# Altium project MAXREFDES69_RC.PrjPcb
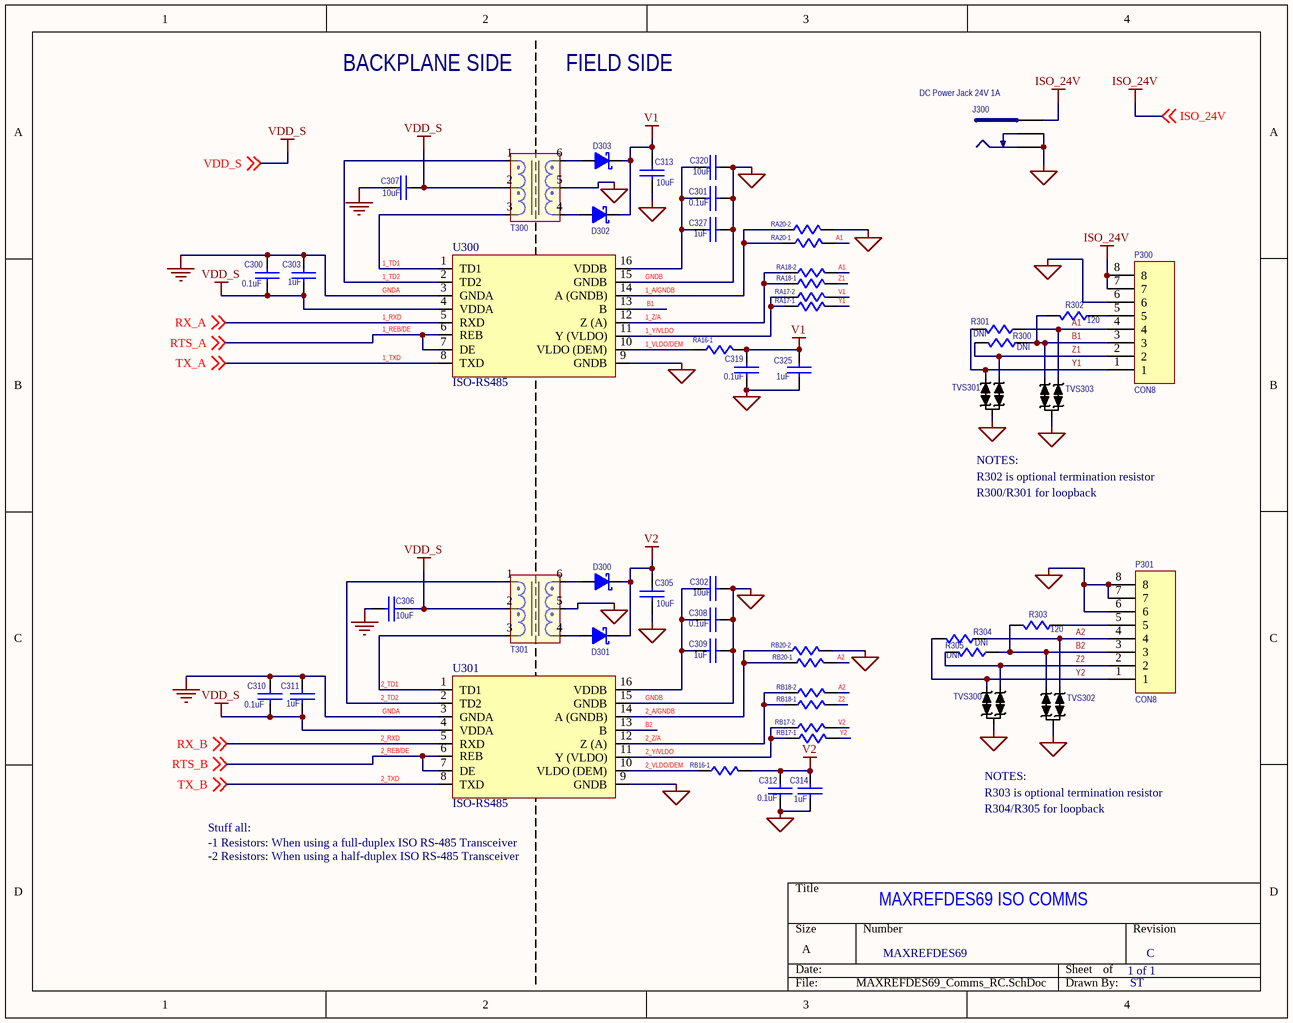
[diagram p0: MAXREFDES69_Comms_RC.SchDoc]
4 sheets, 104 parts. Net scope: global (net labels, ports and power ports of the same name join across sheets).
Board file: MAXREFDES69_PCB_RC.PcbDoc
Sheets:
  MAXREFDES69_Comms_RC.SchDoc
  MAXREFDES69_Power_RC.SchDoc
  MAXREFDES69_Processor_RC.SchDoc
  MAXREFDES69_USB_RC.SchDoc

## Sheet MAXREFDES69_Comms_RC.SchDoc
size A

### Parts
C300  value 0.1uF  [0402]  (hidden comment: CAP)
C301  value 0.1uF  [0402]  (hidden comment: CAP)
C302  value 10uF  [0402]  (hidden comment: CAP)
C303  value 1uF  [0402]  (hidden comment: CAP)
C305  value 10uF  [0402]  (hidden comment: CAP)
C306  value 10uF  [0402]  (hidden comment: CAP)
C307  value 10uF  [0402]  (hidden comment: CAP)
C308  value 0.1uF  [0402]  (hidden comment: CAP)
C309  value 1uF  [0402]  (hidden comment: CAP)
C310  value 0.1uF  [0402]  (hidden comment: CAP)
C311  value 1uF  [0402]  (hidden comment: CAP)
C312  value 0.1uF  [0402]  (hidden comment: CAP)
C313  value 10uF  [0402]  (hidden comment: CAP)
C314  value 1uF  [0402]  (hidden comment: CAP)
C319  value 0.1uF  [0402]  (hidden comment: CAP)
C320  value 10uF  [0402]  (hidden comment: CAP)
C325  value 1uF  [0402]  (hidden comment: CAP)
C327  value 1uF  [0402]  (hidden comment: CAP)
D300  DIODE_SCHOTTKY  [SOD123]  (value not drawn)
D301  DIODE_SCHOTTKY  [SOD123]  (value not drawn)
D302  DIODE_SCHOTTKY  [SOD123]  (value not drawn)
D303  DIODE_SCHOTTKY  [SOD123]  (value not drawn)
J300  DC Power Jack 24V 1A  [JACK\CUI\PJ-202AH]
P300  CON8  [TB\8POS\PHOENIXCONTACT\1771088]
P301  CON8  [TB\8POS\PHOENIXCONTACT\1771088]
R300  value DNI  [R0402]  (hidden comment: RES1)
R301  value DNI  [R0402]  (hidden comment: RES1)
R302  value 120  [R0402]  (hidden comment: RES1)
R303  value 120  [R0402]  (hidden comment: RES1)
R304  value DNI  [R0402]  (hidden comment: RES1)
R305  value DNI  [R0402]  (hidden comment: RES1)
RA16-1  RES1  [R0402]  (value not drawn)
RA17-1  RES1  [R0402]  (value not drawn)
RA17-2  RES1  [R0402]  (value not drawn)
RA18-1  RES1  [R0402]  (value not drawn)
RA18-2  RES1  [R0402]  (value not drawn)
RA20-1  RES1  [R0402]  (value not drawn)
RA20-2  RES1  [R0402]  (value not drawn)
RB16-1  RES1  [R0402]  (value not drawn)
RB17-1  RES1  [R0402]  (value not drawn)
RB17-2  RES1  [R0402]  (value not drawn)
RB18-1  RES1  [R0402]  (value not drawn)
RB18-2  RES1  [R0402]  (value not drawn)
RB20-1  RES1  [R0402]  (value not drawn)
RB20-2  RES1  [R0402]  (value not drawn)
T300  Transformer  [XFMR (WURTH 750315225)]  (value not drawn)
T301  Transformer  [XFMR (WURTH 750315225)]  (value not drawn)
TVS300  TVS SM712  [SM712 TVS]  (value not drawn)
TVS301  TVS SM712  [SM712 TVS]  (value not drawn)
TVS302  TVS SM712  [SM712 TVS]  (value not drawn)
TVS303  TVS SM712  [SM712 TVS]  (value not drawn)
U300  ISO-RS485  [SOIC 16W(W16M-9/10)]
U301  ISO-RS485  [SOIC 16W(W16M-9/10)]

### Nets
GND_S: C300.1 C303.1 C306.2 C307.2 C310.1 C311.1 U300.3(GNDA) U301.3(GNDA)  [also labelled GNDA]
GNDB: C301.1 C302.1 C305.2 C308.1 C309.1 C312.1 C313.2 C314.1 C319.1 C320.1 C325.1 C327.1 J300.2(RETN) J300.3(SENSE) P300.6 P301.6 P301.7 P301.8 RA20-2.2 RB20-2.2 T300.5 T301.5 TVS300.3(K) TVS301.3(K) TVS302.3(K) TVS303.3(K) U300.9(GNDB) U300.15(GNDB) U301.9(GNDB) U301.15(GNDB)  [also labelled ISO_GND]
ISO_24V: J300.1(CTR) P300.7 P300.8 ; off-sheet ISO_24V
V1: C313.1 C319.2 C325.2 D302.2(K) D303.2(K) RA16-1.2 RA17-2.2
V2: C305.1 C312.2 C314.2 D300.2(K) D301.2(K) RB16-1.2 RB17-2.2
VDD_S: C300.2 C303.2 C306.1 C307.1 C310.2 C311.2 T300.2 T301.2 U300.4(VDDA) U301.4(VDDA) ; off-sheet VDD_S
1_A/GNDB: RA20-1.1 RA20-2.1 U300.14(A_(GNDB))
1_REB/DE: U300.6(REB) U300.7(DE) ; off-sheet RTS_A  [also labelled RTS_A]
1_RXD: U300.5(RXD) ; off-sheet RX_A  [also labelled RX_A]
1_TD1: T300.3 U300.1(TD1)
1_TD2: T300.1 U300.2(TD2)
1_TXD: U300.8(TXD) ; off-sheet TX_A  [also labelled TX_A]
1_VLDO/DEM: RA16-1.1 U300.10(VLDO_(DEM))
1_Y/VLDO: RA17-1.1 RA17-2.1 U300.11(Y_(VLDO))
1_Z/A: RA18-1.1 RA18-2.1 U300.12(Z_(A))
2_A/GNDB: RB20-1.1 RB20-2.1 U301.14(A_(GNDB))
2_REB/DE: U301.6(REB) U301.7(DE) ; off-sheet RTS_B  [also labelled RTS_B]
2_RXD: U301.5(RXD) ; off-sheet RX_B  [also labelled RX_B]
2_TD1: T301.3 U301.1(TD1)
2_TD2: T301.1 U301.2(TD2)
2_TXD: U301.8(TXD) ; off-sheet TX_B  [also labelled TX_B]
2_VLDO/DEM: RB16-1.1 U301.10(VLDO_(DEM))
2_Y/VLDO: RB17-1.1 RB17-2.1 U301.11(Y_(VLDO))
2_Z/A: RB18-1.1 RB18-2.1 U301.12(Z_(A))
A1: P300.4 R301.1 RA18-2.2 RA20-1.2 TVS303.2(K)
A2: P301.4 R304.1 RB18-2.2 RB20-1.2 TVS302.2(K)
B1: P300.3 R300.1 R302.2 TVS303.1(K) U300.13(B)
B2: P301.3 R303.2 R305.1 TVS302.1(K) U301.13(B)
Y1: P300.1 R301.2 RA17-1.2 TVS301.1(K)
Y2: P301.1 R304.2 RB17-1.2 TVS300.1(K)
Z1: P300.2 R300.2 RA18-1.2 TVS301.2(K)
Z2: P301.2 R305.2 RB18-1.2 TVS300.2(K)
NetC301_2: C301.2 C320.2 C327.2 U300.16(VDDB)
NetC302_2: C302.2 C308.2 C309.2 U301.16(VDDB)
NetD300_1: D300.1(A) T301.6
NetD301_1: D301.1(A) T301.4
NetD302_1: D302.1(A) T300.4
NetD303_1: D303.1(A) T300.6
NetP300_5: P300.5 R302.1
NetP301_5: P301.5 R303.1

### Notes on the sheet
- BACKPLANE SIDE
- FIELD SIDE
- NOTES:
- R302 is optional termination resistor
- R300/R301 for loopback
- Stuff all:
- R303 is optional termination resistor
- R304/R305 for loopback
- (near U301) -1 Resistors: When using a full-duplex ISO RS-485 Transceiver
- -2 Resistors: When using a half-duplex ISO RS-485 Transceiver
- MAXREFDES69 ISO COMMS
- MAXREFDES69
- 1 of 1
- C
- ST

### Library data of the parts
C300-C303 C305-C314 C319 C320 C325 C327 = CAP: Capacitor
D300-D303 = DIODE_SCHOTTKY: Schottky Diode
J300 = DC Power Jack 24V 1A: DC Power Jack 24V 5A - CUI PJ-202AH
P300 P301 = CON8: Header, 8-pin
T300 T301 = Transformer (RU77)
U300 U301 = ISO_RS485_Combo_1: NOTE: Pin numbers with no notation are RU77/84/85 with TD; NOTE: Pin numbers in () are RU86 (Full duplex)

## Sheet MAXREFDES69_Power_RC.SchDoc
size B
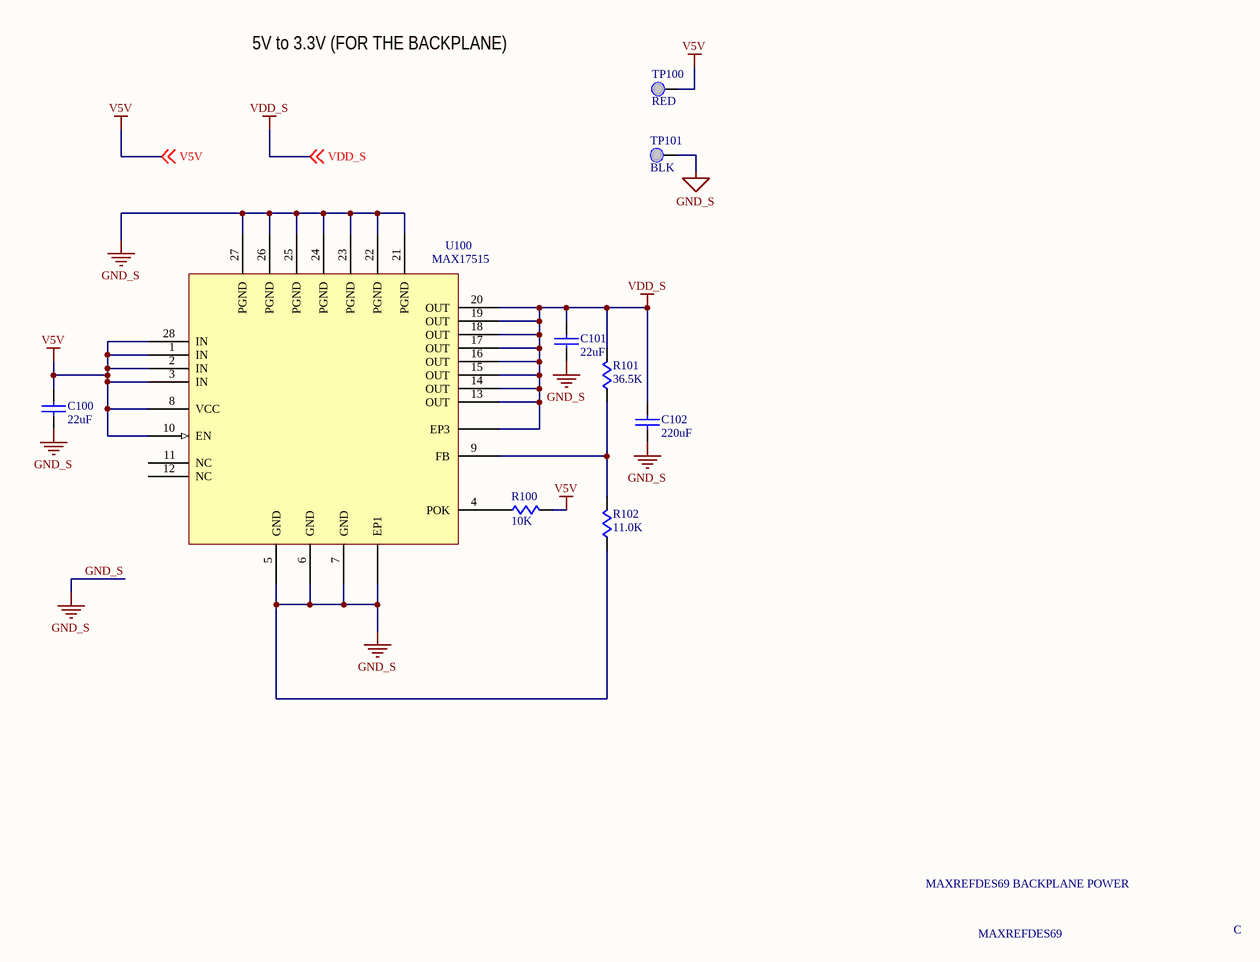
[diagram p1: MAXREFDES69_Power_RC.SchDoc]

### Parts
C100  value 22uF  [1206]  (hidden comment: CAP)
C101  value 22uF  [1206]  (hidden comment: CAP)
C102  value 220uF  [CAP\PANA\TPE\D2E]  (hidden comment: CAP)
R100  value 10K  [R0402]  (hidden comment: RES1)
R101  value 36.5K  [R0402]  (hidden comment: RES1)
R102  value 11.0K  [R0402]  (hidden comment: RES1)
TP100  RED  [TestPoint]
TP101  BLK  [TestPoint]
U100  MAX17515  [SIP28\LGA\6.5X10MM\28L\3EP\L286510+1]

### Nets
EP2: U100.30(EP2) U100.35(EP2) U100.36(EP2) U100.37(EP2)
GND_S: C100.2 C101.2 C102.2 R102.1 TP101.1(PIN) U100.5(GND) U100.6(GND) U100.7(GND) U100.21(PGND) U100.22(PGND) U100.23(PGND) U100.24(PGND) U100.25(PGND) U100.26(PGND) U100.27(PGND) U100.31(EP1) U100.38(EP1) U100.39(EP1) U100.40(EP1) U100.41(EP1) U100.42(EP1)
V5V: C100.1 R100.2 TP100.1(PIN) U100.1(IN) U100.2(IN) U100.3(IN) U100.8(VCC) U100.10(EN) U100.28(IN) ; off-sheet V5V
VDD_S: C101.1 C102.1 R101.2 U100.13(OUT) U100.14(OUT) U100.15(OUT) U100.16(OUT) U100.17(OUT) U100.18(OUT) U100.19(OUT) U100.20(OUT) U100.29(EP3) U100.32(EP3) U100.33(EP3) U100.34(EP3) ; off-sheet VDD_S
NetR100_1: R100.1 U100.4(POK)
NetR101_1: R101.1 R102.2 U100.9(FB)

Not connected (* = marked no-connect by the designer): U100 11(NC) 12(NC)

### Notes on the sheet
- 5V to 3.3V (FOR THE BACKPLANE)
- MAXREFDES69 BACKPLANE POWER
- MAXREFDES69
- C

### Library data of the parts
C100-C102 = CAP: Capacitor
TP100 TP101 = TESTPOINT: Test Point Loop

## Sheet MAXREFDES69_Processor_RC.SchDoc
size B
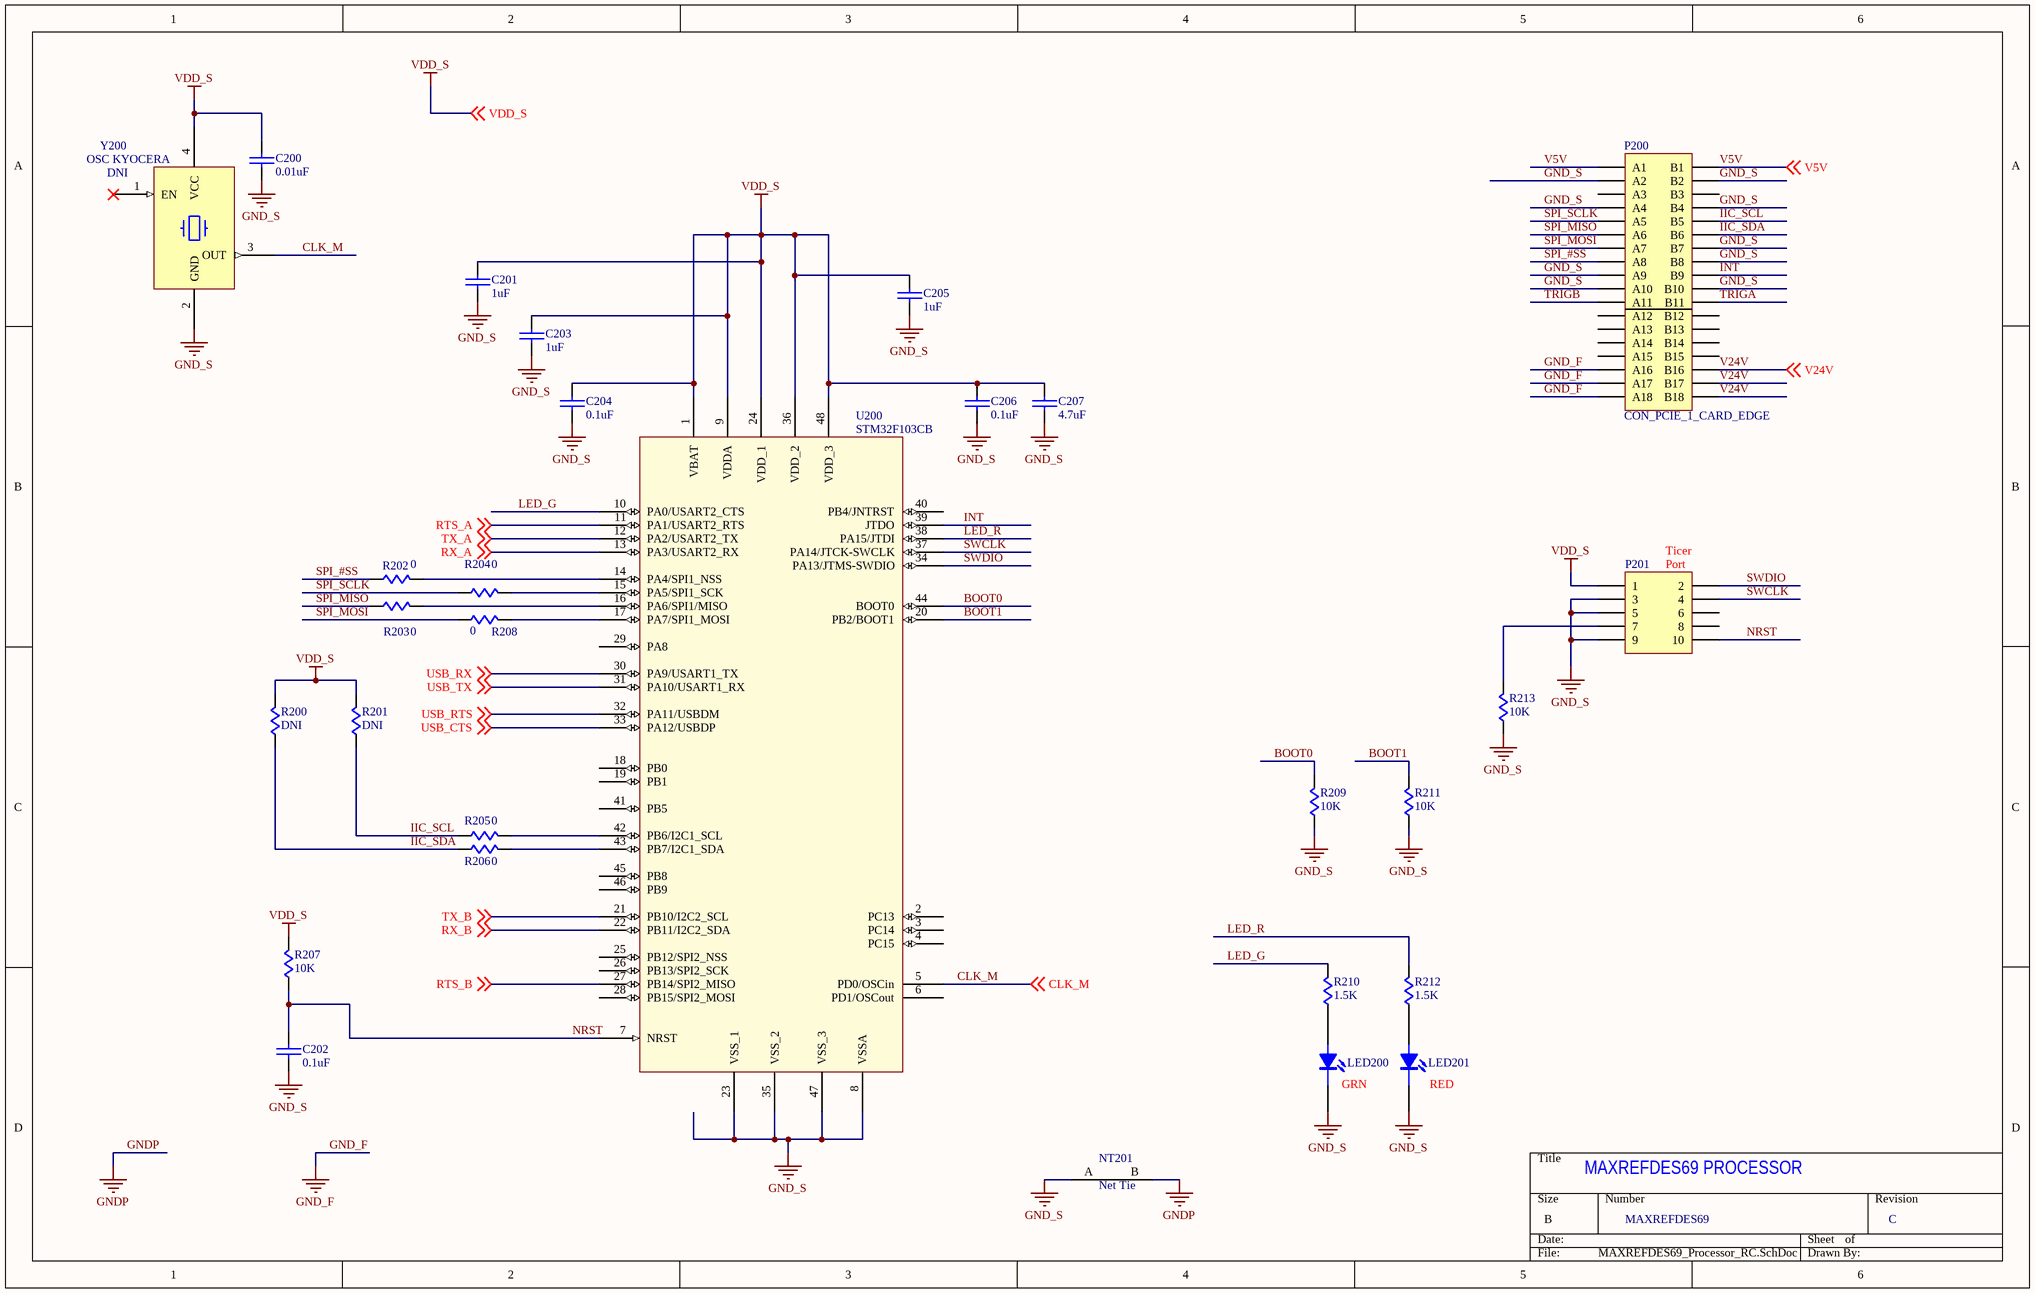
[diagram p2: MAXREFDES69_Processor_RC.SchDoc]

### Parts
C200  value 0.01uF  [0603]  (hidden comment: CAP)
C201  value 1uF  [0603]  (hidden comment: CAP)
C202  value 0.1uF  [0603]  (hidden comment: CAP)
C203  value 1uF  [0603]  (hidden comment: CAP)
C204  value 0.1uF  [0603]  (hidden comment: CAP)
C205  value 1uF  [0603]  (hidden comment: CAP)
C206  value 0.1uF  [0603]  (hidden comment: CAP)
C207  value 4.7uF  [0603]  (hidden comment: CAP)
LED200  LED  [LED\ROHM\SML-P1]  (value not drawn)
LED201  LED  [LED\ROHM\SML-P1]  (value not drawn)
NT201  Net Tie  [Net Tie Small 2]  (net tie, no BOM)
P200  CON_PCIE_1_CARD_EDGE  [CONN\PCI_EXP\36P\CARDEDGE\GLPMSS]
P201  HEADER 5X2  [CONN\SAMTEC\FTSH-105-01-L-DV-K]  (value not drawn)
R200  value DNI  [R0402]  (hidden comment: RES1)
R201  value DNI  [R0402]  (hidden comment: RES1)
R202  value 0  [R0402]  (hidden comment: RES1)
R203  value 0  [R0402]  (hidden comment: RES1)
R204  value 0  [R0402]  (hidden comment: RES1)
R205  value 0  [R0402]  (hidden comment: RES1)
R206  value 0  [R0402]  (hidden comment: RES1)
R207  value 10K  [R0402]  (hidden comment: RES1)
R208  value 0  [R0402]  (hidden comment: RES1)
R209  value 10K  [R0402]  (hidden comment: RES1)
R210  value 1.5K  [R0402]  (hidden comment: RES1)
R211  value 10K  [CC0402]  (hidden comment: CC0402)
R212  value 1.5K  [CC0402]  (hidden comment: RES1)
R213  value 10K  [R0402]  (hidden comment: RES1)
U200  STM32F103CB  [LQFP48 - ST Micro]
Y200  OSC KYOCERA  [XTAL\HOSONIC\2520]

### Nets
GND_F: P200.A16 P200.A17 P200.A18
GND_S: C200.2 C201.2 C202.2 C203.2 C204.2 C205.2 C206.2 C207.2 LED200.2(K) LED201.2(K) P200.A2 P200.A4 P200.A9 P200.A10 P200.B2 P200.B4 P200.B7 P200.B8 P200.B10 P201.3 P201.5 P201.9 R209.1 R211.1 R213.1 U200.8(VSSA) U200.23(VSS_1) U200.35(VSS_2) U200.47(VSS_3) Y200.2(GND)
V5V: P200.A1 P200.B1 ; off-sheet V5V
VDD_S: C200.1 C201.1 C203.1 C204.1 C205.1 C206.1 C207.1 P201.1 R200.2 R201.2 R207.2 U200.1(VBAT) U200.9(VDDA) U200.24(VDD_1) U200.36(VDD_2) U200.48(VDD_3) Y200.4(VCC) ; off-sheet VDD_S
BOOT0: R209.2 U200.44(BOOT0)
BOOT1: R211.2 U200.20(PB2/BOOT1)
CLK_M: U200.5(PD0/OSCin) Y200.3(OUT) ; off-sheet CLK_M
IIC_SCL: P200.B5 R201.1 R205.1
IIC_SDA: P200.B6 R200.1 R206.1
INT: P200.B9 U200.39(JTDO)
LED_G: R210.2 U200.10(PA0/USART2_CTS)
LED_R: R212.2 U200.38(PA15/JTDI)
NRST: C202.1 P201.10 R207.1 U200.7(NRST)
RTS_A: U200.11(PA1/USART2_RTS) ; off-sheet RTS_A  [project net 1_REB/DE]
RTS_B: U200.27(PB14/SPI2_MISO) ; off-sheet RTS_B  [project net 2_REB/DE]
RX_A: U200.13(PA3/USART2_RX) ; off-sheet RX_A  [project net 1_RXD]
RX_B: U200.22(PB11/I2C2_SDA) ; off-sheet RX_B  [project net 2_RXD]
SPI_#SS: P200.A8 R202.1
SPI_MISO: P200.A6 R203.1
SPI_MOSI: P200.A7 R208.1
SPI_SCLK: P200.A5 R204.1
SWCLK: P201.4 U200.37(PA14/JTCK-SWCLK)
SWDIO: P201.2 U200.34(PA13/JTMS-SWDIO)
TRIGA: P200.B11
TRIGB: P200.A11
TX_A: U200.12(PA2/USART2_TX) ; off-sheet TX_A  [project net 1_TXD]
TX_B: U200.21(PB10/I2C2_SCL) ; off-sheet TX_B  [project net 2_TXD]
USB_CTS: U200.33(PA12/USBDP) ; off-sheet USB_CTS
USB_RTS: U200.32(PA11/USBDM) ; off-sheet USB_RTS
USB_RX: U200.30(PA9/USART1_TX) ; off-sheet USB_RX
USB_TX: U200.31(PA10/USART1_RX) ; off-sheet USB_TX
V24V: P200.B16 P200.B17 P200.B18 ; off-sheet V24V
NetLED200_1: LED200.1(A) R210.1
NetLED201_1: LED201.1(A) R212.1
NetNT201_A: NT201.A NT201.B
NetP201_7: P201.7 R213.2
NetR202_2: R202.2 U200.14(PA4/SPI1_NSS)
NetR203_2: R203.2 U200.16(PA6/SPI1/MISO)
NetR204_2: R204.2 U200.15(PA5/SPI1_SCK)
NetR205_2: R205.2 U200.42(PB6/I2C1_SCL)
NetR206_2: R206.2 U200.43(PB7/I2C1_SDA)
NetR208_2: R208.2 U200.17(PA7/SPI1_MOSI)

Not connected (* = marked no-connect by the designer): P200 A3 A12 A13 A14 A15 B3 B12 B13 B14 B15; P201 6 8; U200 2(PC13) 3(PC14) 4(PC15) 6(PD1/OSCout) 18(PB0) 19(PB1) 25(PB12/SPI2_NSS) 26(PB13/SPI2_SCK) 28(PB15/SPI2_MOSI) 29(PA8) 40(PB4/JNTRST) 41(PB5) 45(PB8) 46(PB9); Y200 1(EN)*

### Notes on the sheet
- (near P201) Ticer
- (near P201) Port
- (near LED200) GRN
- (near LED201) RED
- MAXREFDES69 PROCESSOR
- MAXREFDES69
- C

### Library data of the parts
C200-C207 = CAP: Capacitor
P200 = CON_PCIE_1_STATIC: PCIE-1, FCI 10018783-10200TLF
R211 = RES1
U200 = STM32F103CB: STM32F103 Micorprocessor
Y200 = OSC_KYOCERA: Osc, Kyocera

## Sheet MAXREFDES69_USB_RC.SchDoc
size B
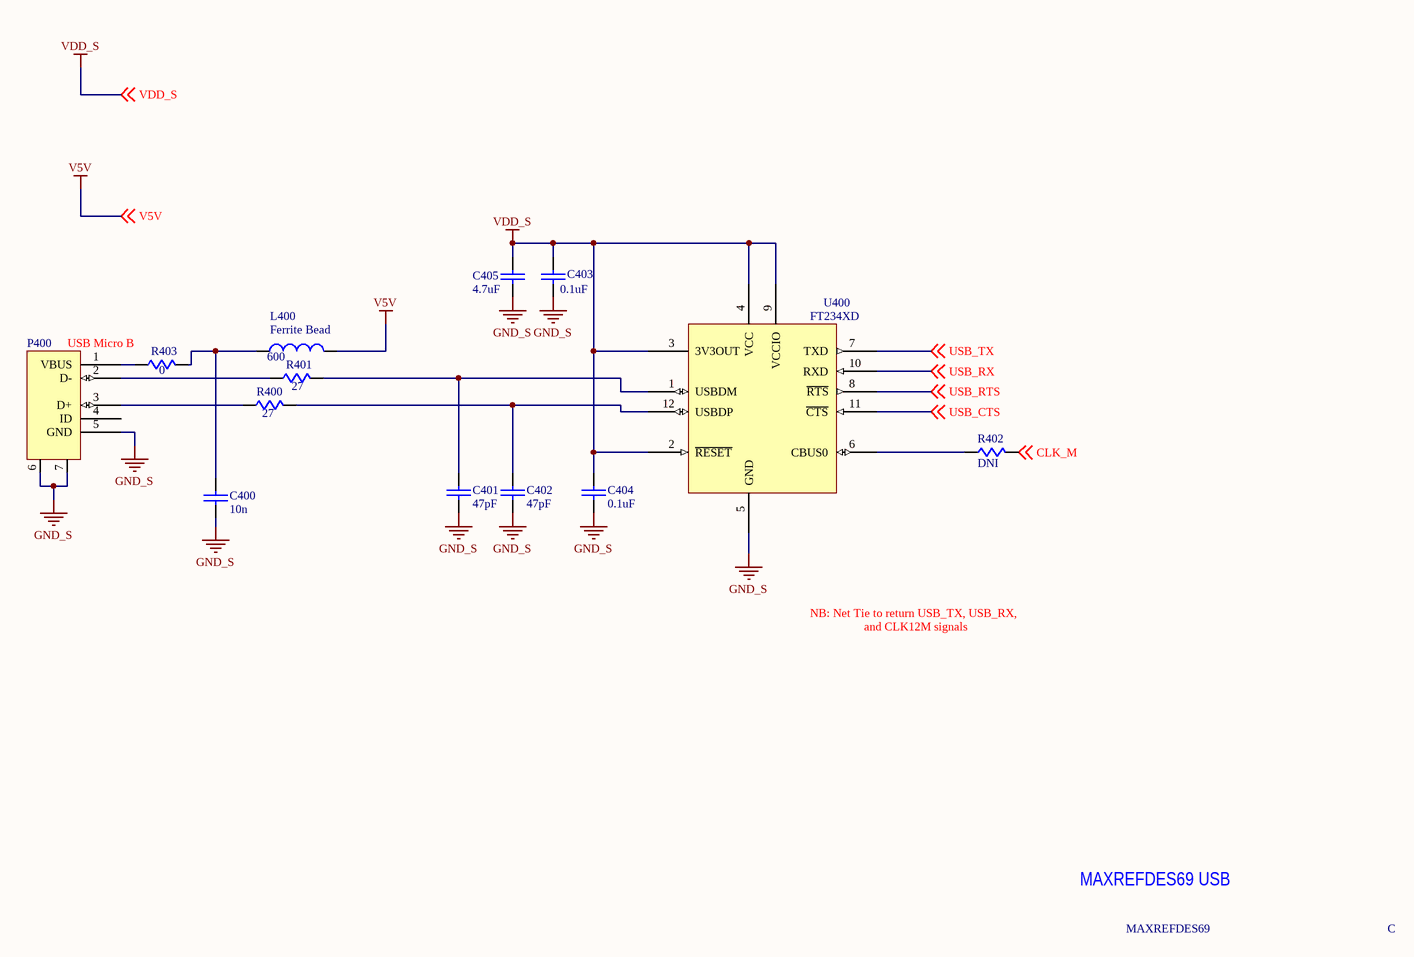
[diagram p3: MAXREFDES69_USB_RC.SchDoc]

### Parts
C400  value 10n  [CC0402]  (hidden comment: CAP)
C401  value 47pF  [CC0402]  (hidden comment: CAP)
C402  value 47pF  [CC0402]  (hidden comment: CAP)
C403  value 0.1uF  [CC0402]  (hidden comment: CAP)
C404  value 0.1uF  [CC0402]  (hidden comment: CAP)
C405  value 4.7uF  [CC0402]  (hidden comment: CAP)
L400  Ferrite Bead  value 600  [R0805]
P400  CONN\HIROSE\ZX62RD-AB-5P8\MICRO_AB  [CONN\HIROSE\ZX62RD-AB-5P8\MICRO_AB]  (value not drawn)
R400  value 27  [CC0603]  (hidden comment: RES1)
R401  value 27  [CC0603]  (hidden comment: RES1)
R402  value DNI  [R0402]  (hidden comment: RES1)
R403  value 0  [R0402]  (hidden comment: RES1)
U400  FT234XD  [DFN\3X3MM\12L\EP]

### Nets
GND_S: C400.2 C401.2 C402.2 C403.2 C404.2 C405.2 P400.5(GND) P400.6(S) P400.7(S) P400.8(GND) P400.9(GND) P400.10(GND) U400.5(GND) U400.13(GND) U400.14(GND) U400.15(GND) U400.16(EP)
V5V: L400.2 ; off-sheet V5V
VDD_S: C403.1 C404.1 C405.1 U400.2(~{RESET}) U400.3(3V3OUT) U400.4(VCC) U400.9(VCCIO) ; off-sheet VDD_S
CLK_M: R402.2 ; off-sheet CLK_M
USB_CTS: U400.11(~{CTS}) ; off-sheet USB_CTS
USB_RTS: U400.8(~{RTS}) ; off-sheet USB_RTS
USB_RX: U400.10(RXD) ; off-sheet USB_RX
USB_TX: U400.7(TXD) ; off-sheet USB_TX
NetC400_1: C400.1 L400.1 R403.2
NetC401_1: C401.1 R401.2 U400.1(USBDM)
NetC402_1: C402.1 R400.2 U400.12(USBDP)
NetP400_1: P400.1(VBUS) R403.1
NetP400_2: P400.2(D-) R401.1
NetP400_3: P400.3(D+) R400.1
NetR402_1: R402.1 U400.6(CBUS0)

Not connected (* = marked no-connect by the designer): P400 4(ID)

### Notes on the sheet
- USB Micro B
- NB: Net Tie to return USB_TX, USB_RX,
- and CLK12M signals
- MAXREFDES69 USB
- MAXREFDES69
- C

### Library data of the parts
C400-C405 = CAP: Capacitor
L400 = Inductor: Code_IEC: 1005
P400 = USB_MINI_B: USB Micro B Connector
U400 = FT234XD: USB - Serial, SSOP

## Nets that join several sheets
GND_S: MAXREFDES69_Comms_RC (8 pins), MAXREFDES69_Power_RC (21 pins), MAXREFDES69_Processor_RC (30 pins), MAXREFDES69_USB_RC (17 pins)
V5V: MAXREFDES69_Power_RC (9 pins), MAXREFDES69_Processor_RC (P200.A1 P200.B1), MAXREFDES69_USB_RC (L400.2)
VDD_S: MAXREFDES69_Comms_RC (10 pins), MAXREFDES69_Power_RC (15 pins), MAXREFDES69_Processor_RC (17 pins), MAXREFDES69_USB_RC (7 pins)
1_REB/DE: MAXREFDES69_Comms_RC (U300.6 U300.7), MAXREFDES69_Processor_RC (U200.11)
1_RXD: MAXREFDES69_Comms_RC (U300.5), MAXREFDES69_Processor_RC (U200.13)
1_TXD: MAXREFDES69_Comms_RC (U300.8), MAXREFDES69_Processor_RC (U200.12)
2_REB/DE: MAXREFDES69_Comms_RC (U301.6 U301.7), MAXREFDES69_Processor_RC (U200.27)
2_RXD: MAXREFDES69_Comms_RC (U301.5), MAXREFDES69_Processor_RC (U200.22)
2_TXD: MAXREFDES69_Comms_RC (U301.8), MAXREFDES69_Processor_RC (U200.21)
CLK_M: MAXREFDES69_Processor_RC (U200.5 Y200.3), MAXREFDES69_USB_RC (R402.2)
USB_CTS: MAXREFDES69_Processor_RC (U200.33), MAXREFDES69_USB_RC (U400.11)
USB_RTS: MAXREFDES69_Processor_RC (U200.32), MAXREFDES69_USB_RC (U400.8)
USB_RX: MAXREFDES69_Processor_RC (U200.30), MAXREFDES69_USB_RC (U400.10)
USB_TX: MAXREFDES69_Processor_RC (U200.31), MAXREFDES69_USB_RC (U400.7)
